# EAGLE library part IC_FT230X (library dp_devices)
BASIC USB to UART IC
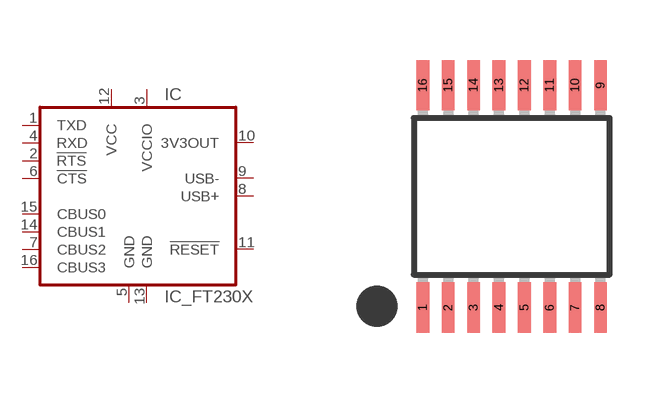
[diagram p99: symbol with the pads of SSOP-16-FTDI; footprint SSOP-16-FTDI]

Designator prefix IC

## IC_FT230X-SSOP-16  [SSOP-16-FTDI]
1  TXD  out
2  !RTS
3  VCCIO  pwr
4  RXD  in
5  GND  sup
6  !CTS
7  CBUS2
8  USB+  out
9  USB-  in
10  3V3OUT  pwr
11  !RESET
12  VCC  sup
13  GND  sup
14  CBUS1
15  CBUS0
16  CBUS3

## Footprint SSOP-16-FTDI (pad centres in mm)
SSOP-16, 0.32 x 1.26 mm pad, 0.63mm pitch, 6.82mm Pad length
smd 0.32 x 1.26: 1 -2.223,-2.779; 2 -1.588,-2.779; 3 -0.953,-2.779; 4 -0.318,-2.779; 5 0.317,-2.779; 6 0.952,-2.779; 7 1.587,-2.779; 8 2.222,-2.779; 9 2.222,2.779; 10 1.587,2.779; 11 0.952,2.779; 12 0.317,2.779; 13 -0.318,2.779; 14 -0.953,2.779; 15 -1.588,2.779; 16 -2.223,2.779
